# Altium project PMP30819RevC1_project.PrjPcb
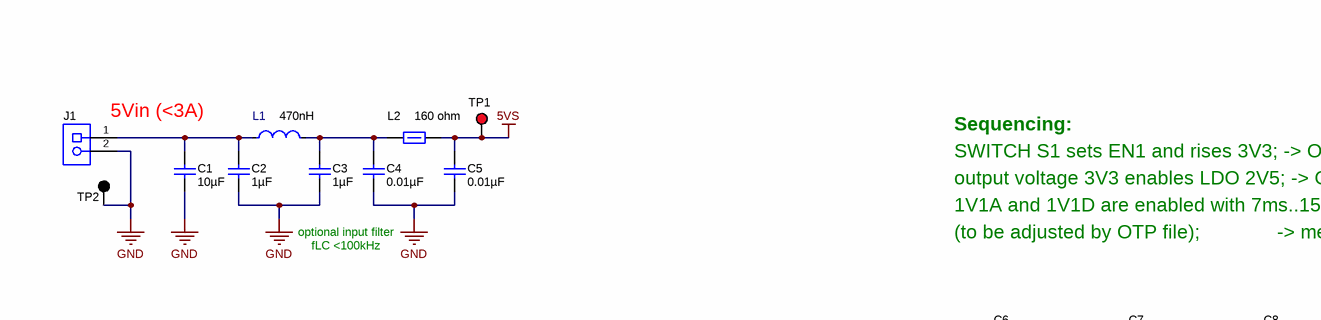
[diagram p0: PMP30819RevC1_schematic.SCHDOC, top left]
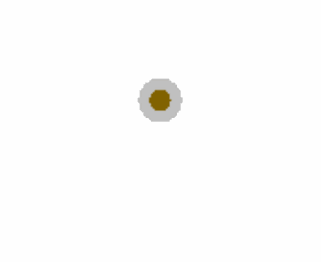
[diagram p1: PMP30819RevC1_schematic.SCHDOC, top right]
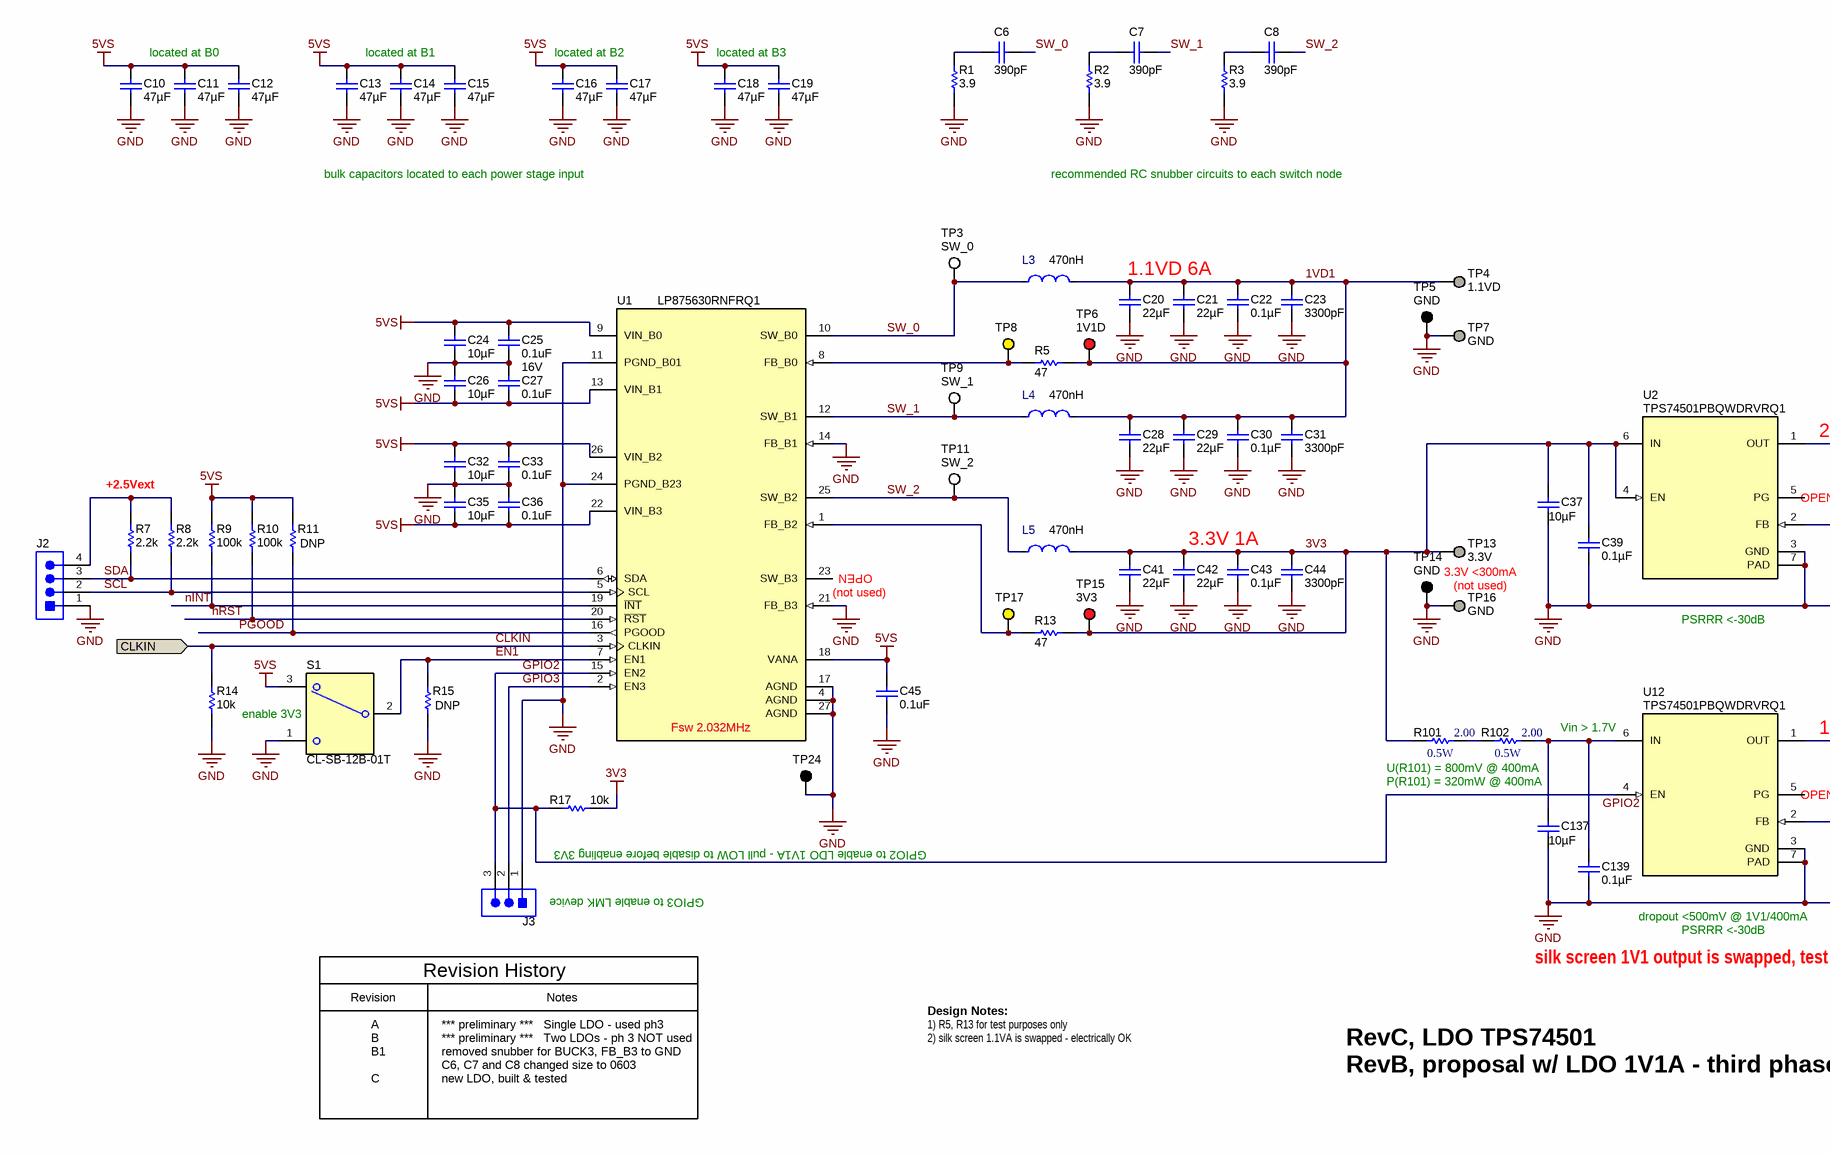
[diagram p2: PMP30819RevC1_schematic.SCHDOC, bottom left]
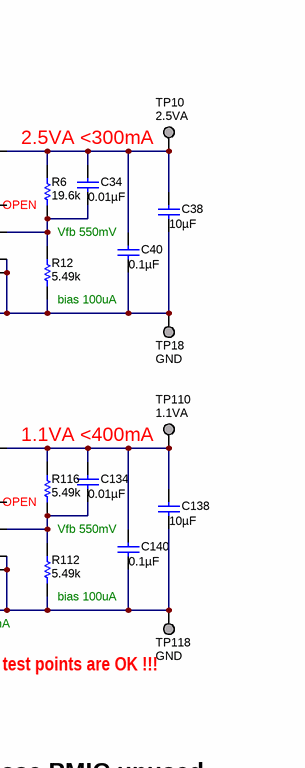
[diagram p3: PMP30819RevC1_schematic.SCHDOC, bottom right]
TID: N/A; TechSupport: http://www.ti.com/support; SCH_Rev: C1; PRJ_Title: Automotive Supply using PMIC; PRJ_Number: PMP30819; PRJ_Engineer: B.Geck; PRJ_Customer: Public Release; PCB_Rev: C1; CopyrightYear: 2020
1 sheet, 100 parts. Net scope: flat (ports and power ports of the same name join across sheets).
Board file: PMP30819RevC1_board.PcbDoc

## Sheet PMP30819RevC1_schematic.SCHDOC: PMP30819RevC1
size A3; Date: Not shown in title block; ApprovedBy: Not shown in title block; CheckedBy: Not shown in title block; Author: Not shown in title block; CompanyName: Not shown in title block; DrawnBy: B.Geck; Engineer: Not shown in title block; Organization: Not shown in title block; Address1: Not shown in title block; Address2: Not shown in title block; Address3: Not shown in title block; Address4: Not shown in title block; DocumentNumber: 1; Revision: Use project parameter SCH_Rev; SheetNumber: 1; SheetTotal: 1; PageSetup: Record=PageOptions¦CenterHorizontal=True¦CenterVertical=True¦PrintScale=0.70¦XCorrection=1.00¦YCorrection=1.00¦PrintKind=0¦BorderSize=5000000¦LeftOffset=0¦BottomOffset=0¦Orientation=2¦PaperLength=1000¦PaperWidth=1000¦Scale=100¦PaperSource=15¦PrintQuality=600¦MediaType=1¦DitherType=10¦PaperKind=A4¦PrintScaleMode=1

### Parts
C1  ValueDisplayed: 10µF  [0805_HV]  (hidden comment: CL21B106KOQNNNE)
C2  ValueDisplayed: 1µF  [0603]  (hidden comment: GRM188R71C105KA12D)
C3  ValueDisplayed: 1µF  [0603]  (hidden comment: GRM188R71C105KA12D)
C4  ValueDisplayed: 0.01µF  [0603]  (hidden comment: GRM188R71C103KA01D)
C5  ValueDisplayed: 0.01µF  [0603]  (hidden comment: GRM188R71C103KA01D)
C6  Cap_F: 390pF  [0603]  (hidden comment: GRM188R71H391KA01D)
C7  Cap_F: 390pF  [0603]  (hidden comment: GRM188R71H391KA01D)
C8  Cap_F: 390pF  [0603]  (hidden comment: GRM188R71H391KA01D)
C10  ValueDisplayed: 47µF  [1210_270]  (hidden comment: LMK325B7476MM-TR)
C11  ValueDisplayed: 47µF  [1210_270]  (hidden comment: LMK325B7476MM-TR)
C12  ValueDisplayed: 47µF  [1210_270]  (hidden comment: LMK325B7476MM-TR)
C13  ValueDisplayed: 47µF  [1210_270]  (hidden comment: LMK325B7476MM-TR)
C14  ValueDisplayed: 47µF  [1210_270]  (hidden comment: LMK325B7476MM-TR)
C15  ValueDisplayed: 47µF  [1210_270]  (hidden comment: LMK325B7476MM-TR)
C16  ValueDisplayed: 47µF  [1210_270]  (hidden comment: LMK325B7476MM-TR)
C17  ValueDisplayed: 47µF  [1210_270]  (hidden comment: LMK325B7476MM-TR)
C18  ValueDisplayed: 47µF  [1210_270]  (hidden comment: LMK325B7476MM-TR)
C19  ValueDisplayed: 47µF  [1210_270]  (hidden comment: LMK325B7476MM-TR)
C20  ValueDisplayed: 22µF  [1206_190]  (hidden comment: GRJ31CR71A226KE12L)
C21  ValueDisplayed: 22µF  [1206_190]  (hidden comment: GRJ31CR71A226KE12L)
C22  ValueDisplayed: 0.1µF  [0603]  (hidden comment: GCM188R71C104KA37J)
C23  ValueDisplayed: 3300pF  [0402L]  (hidden comment: CGA2B2X7R1H332K050BA)
C24  ValueDisplayed: 10µF  [0805_HV]  (hidden comment: CL21B106KOQNNNE)
C25  ValueDisplayed: 0.1uF  VDC_V: 16V  [0402L]  (hidden comment: C0402C104K4RACAUTO)
C26  ValueDisplayed: 10µF  [0805_HV]  (hidden comment: CL21B106KOQNNNE)
C27  ValueDisplayed: 0.1uF  [0402L]  (hidden comment: C0402C104K4RACAUTO)
C28  ValueDisplayed: 22µF  [1206_190]  (hidden comment: GRJ31CR71A226KE12L)
C29  ValueDisplayed: 22µF  [1206_190]  (hidden comment: GRJ31CR71A226KE12L)
C30  ValueDisplayed: 0.1µF  [0603]  (hidden comment: GCM188R71C104KA37J)
C31  ValueDisplayed: 3300pF  [0402L]  (hidden comment: CGA2B2X7R1H332K050BA)
C32  ValueDisplayed: 10µF  [0805_HV]  (hidden comment: CL21B106KOQNNNE)
C33  ValueDisplayed: 0.1uF  [0402L]  (hidden comment: C0402C104K4RACAUTO)
C34  ValueDisplayed: 0.01µF  [0603]  (hidden comment: GRM188R71C103KA01D)
C35  ValueDisplayed: 10µF  [0805_HV]  (hidden comment: CL21B106KOQNNNE)
C36  ValueDisplayed: 0.1uF  [0402L]  (hidden comment: C0402C104K4RACAUTO)
C37  ValueDisplayed: 10µF  [0805_HV]  (hidden comment: CL21B106KOQNNNE)
C38  ValueDisplayed: 10µF  [0805_HV]  (hidden comment: CL21B106KOQNNNE)
C39  ValueDisplayed: 0.1µF  [0603]  (hidden comment: GCM188R71C104KA37J)
C40  ValueDisplayed: 0.1µF  [0603]  (hidden comment: GCM188R71C104KA37J)
C41  ValueDisplayed: 22µF  [1206_190]  (hidden comment: GRJ31CR71A226KE12L)
C42  ValueDisplayed: 22µF  [1206_190]  (hidden comment: GRJ31CR71A226KE12L)
C43  ValueDisplayed: 0.1µF  [0603]  (hidden comment: GCM188R71C104KA37J)
C44  ValueDisplayed: 3300pF  [0402L]  (hidden comment: CGA2B2X7R1H332K050BA)
C45  ValueDisplayed: 0.1uF  [0402L]  (hidden comment: C0402C104K4RACAUTO)
C134  ValueDisplayed: 0.01µF  [0603]  (hidden comment: GRM188R71C103KA01D)
C137  ValueDisplayed: 10µF  [0805_HV]  (hidden comment: CL21B106KOQNNNE)
C138  ValueDisplayed: 10µF  [0805_HV]  (hidden comment: CL21B106KOQNNNE)
C139  ValueDisplayed: 0.1µF  [0603]  (hidden comment: GCM188R71C104KA37J)
C140  ValueDisplayed: 0.1µF  [0603]  (hidden comment: GCM188R71C104KA37J)
J1  ED555/2DS  [TERM_BLK_ED555-2DS]  (value not drawn)
J2  800-10-004-10-001000  [Mill-Max_800-10-004-10-001000]  (value not drawn)
J3  800-10-003-10-001000  [Mill-Max_800-10-003-10-001000]  (value not drawn)
L1  Ind_H: 470nH  [FP-XGL4020-471MEC_SMT_4MM0_4MM0-MFG]  (hidden comment: XGL4020-471MEC)
L2  ValueDisplayed: 160 ohm  [1206]  (hidden comment: HI1206T161R-10)
L3  Ind_H: 470nH  [FP-XGL4020-471MEC_SMT_4MM0_4MM0-MFG]  (hidden comment: XGL4020-471MEC)
L4  Ind_H: 470nH  [FP-XGL4020-471MEC_SMT_4MM0_4MM0-MFG]  (hidden comment: XGL4020-471MEC)
L5  Ind_H: 470nH  [FP-XGL4020-471MEC_SMT_4MM0_4MM0-MFG]  (hidden comment: XGL4020-471MEC)
R1  ValueDisplayed: 3.9  [0805_HV]  (hidden comment: CRCW08053R90JNEA)
R2  ValueDisplayed: 3.9  [0805_HV]  (hidden comment: CRCW08053R90JNEA)
R3  ValueDisplayed: 3.9  [0805_HV]  (hidden comment: CRCW08053R90JNEA)
R5  ValueDisplayed: 47  [0603]  (hidden comment: CRCW060347R0JNEA)
R6  ValueDisplayed: 19.6k  [0603]  (hidden comment: CRCW060319K6FKEA)
R7  ValueDisplayed: 2.2k  [0603]  (hidden comment: CRCW06032K20JNEA)
R8  ValueDisplayed: 2.2k  [0603]  (hidden comment: CRCW06032K20JNEA)
R9  ValueDisplayed: 100k  [0603]  (hidden comment: CRCW0603100KFKEA)
R10  ValueDisplayed: 100k  [0603]  (hidden comment: CRCW0603100KFKEA)
R11  DNP  [0603]
R12  ValueDisplayed: 5.49k  [0603]  (hidden comment: CRCW06035K49FKEA)
R13  ValueDisplayed: 47  [0603]  (hidden comment: CRCW060347R0JNEA)
R14  ValueDisplayed: 10k  [0603]  (hidden comment: CRCW060310K0JNEA)
R15  DNP  [0603]
R17  ValueDisplayed: 10k  [0603]  (hidden comment: CRCW060310K0JNEA)
R101  ValueDisplayed: 2.00  Value2: 0.5W  [1210M]  (hidden comment: ERJ-14BQF2R0U)
R102  ValueDisplayed: 2.00  Value2: 0.5W  [1210M]  (hidden comment: ERJ-14BQF2R0U)
R112  ValueDisplayed: 5.49k  [0603]  (hidden comment: CRCW06035K49FKEA)
R116  ValueDisplayed: 5.49k  [0603]  (hidden comment: CRCW06035K49FKEA)
S1  CL-SB-12B-01T  [SW_CL-SB-12B-01]
TP1  5010  [Keystone5010]  (value not drawn)
TP2  5011  [Keystone5011]  (value not drawn)
TP3  SW_0  [Keystone5012]
TP4  1.1VD  [Keystone1503-2]
TP5  GND  [Keystone5011]
TP6  1V1D  [Keystone5010]
TP7  GND  [Keystone1503-2]
TP8  5014  [Keystone5014]  (value not drawn)
TP9  SW_1  [Keystone5012]
TP10  2.5VA  [Keystone1503-2]
TP11  SW_2  [Keystone5012]
TP13  3.3V  [Keystone1503-2]
TP14  GND  [Keystone5011]
TP15  3V3  [Keystone5010]
TP16  GND  [Keystone1503-2]
TP17  5014  [Keystone5014]  (value not drawn)
TP18  GND  [Keystone1503-2]
TP24  5011  [Keystone5011]  (value not drawn)
TP110  1.1VA  [Keystone1503-2]
TP118  GND  [Keystone1503-2]
U1  LP875630RNFRQ1  [RNF0026C]
U2  PartNumber: TPS74501PBQWDRVRQ1  [DRV0006A]  (hidden comment: TPS74501PDRVR)
U12  PartNumber: TPS74501PBQWDRVRQ1  [DRV0006A]  (hidden comment: TPS74501PDRVR)

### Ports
CLKIN (in)

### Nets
3V3: C37.1 C39.2 C41.1 C42.1 C43.2 C44.1 L5.2 R13.2 R17.2 R101.1 TP13.1 TP15.1 U2.4(EN) U2.6(IN)
5VS: C5.1 C10.1 C11.1 C12.1 C13.1 C14.1 C15.2 C16.1 C17.1 C18.1 C19.1 C24.1 C25.2 C26.1 C27.1 C32.1 C33.2 C35.1 C36.1 C45.1 L2.2 R9.1 R10.1 R11.1 S1.3 TP1.1 U1.9(VIN_B0) U1.13(VIN_B1) U1.18(VANA) U1.22(VIN_B3) U1.26(VIN_B2)
GND: C1.2 C2.2 C3.2 C4.2 C5.2 C10.2 C11.2 C12.2 C13.2 C14.2 C15.1 C16.2 C17.2 C18.2 C19.2 C20.2 C21.2 C22.1 C23.2 C24.2 C25.1 C26.2 C27.2 C28.2 C29.2 C30.1 C31.2 C32.2 C33.1 C35.2 C36.2 C37.2 C38.2 C39.1 C40.1 C41.2 C42.2 C43.1 C44.2 C45.2 C137.2 C138.2 C139.1 C140.1 J1.2 J2.1 J3.1 R1.1 R2.1 R3.1 R12.1 R14.2 R15.1 R112.1 S1.1 TP2.1 TP5.1 TP7.1 TP14.1 TP16.1 TP18.1 TP24.1 TP118.1 U1.4(AGND) U1.11(PGND_B01) U1.14(FB_B1) U1.17(AGND) U1.21(FB_B3) U1.24(PGND_B23) U1.27(AGND) U2.3(GND) U2.7(PAD) U12.3(GND) U12.7(PAD)
1VD1: C20.1 C21.1 C22.2 C23.1 C28.1 C29.1 C30.2 C31.1 L3.2 L4.2 R5.2 TP4.1 TP6.1
CLKIN: R14.1 U1.3(CLKIN) ; port CLKIN
EN1: R15.2 S1.2(COM) U1.7(EN1)
GPIO2: J3.3 R17.1 U1.15(EN2) U12.4(EN)
GPIO3: J3.2 U1.2(EN3)
nINT: R9.2 U1.19(~{INT})
nRST: R10.2 U1.20(~{RST})
PGOOD: R11.2 U1.16(PGOOD)
SCL: J2.2 R8.2 U1.5(SCL)
SDA: J2.3 R7.2 U1.6(SDA)
SW_0: C6.1 L3.1 TP3.1 U1.10(SW_B0)
SW_1: C7.1 L4.1 TP9.1 U1.12(SW_B1)
SW_2: C8.1 L5.1 TP11.1 U1.25(SW_B2)
NetC1_1: C1.1 C2.1 J1.1 L1.1
NetC3_1: C3.1 C4.1 L1.2 L2.1
NetC6_2: C6.2 R1.2
NetC7_2: C7.2 R2.2
NetC8_2: C8.2 R3.2
NetC34_1: C34.1 C38.1 C40.2 R6.2 TP10.1 U2.1(OUT)
NetC34_2: C34.2 R6.1 R12.2 U2.2(FB)
NetC134_1: C134.1 C138.1 C140.2 R116.2 TP110.1 U12.1(OUT)
NetC134_2: C134.2 R112.2 R116.1 U12.2(FB)
NetC137_1: C137.1 C139.2 R102.2 U12.6(IN)
NetJ2_4: J2.4 R7.1 R8.1
NetR5_1: R5.1 TP8.1 U1.8(FB_B0)
NetR13_1: R13.1 TP17.1 U1.1(FB_B2)
NetR101_2: R101.2 R102.1

Not connected (* = marked no-connect by the designer): U1 23(SW_B3); U2 5(PG); U12 5(PG)

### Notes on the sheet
- (near J1) 5Vin (<3A)
- Sequencing:
- SWITCH S1 sets EN1 and rises 3V3; -> O.K.
- optional input filter
- output voltage 3V3 enables LDO 2V5; -> O.K.
- 1V1A and 1V1D are enabled with 7ms..15ms delay regarding rise of 2V5.
- (to be adjusted by OTP file);              -> measured delay around 11ms, O.K.
- fLC <100kHz
- located at B0
- located at B1
- located at B2
- located at B3
- bulk capacitors located to each power stage input
- recommended RC snubber circuits to each switch node
- 1.1VD 6A
- (near U1) 8.5Amax
- +2.5Vext
- 2.5VA <300mA
- (near U1) 1.3Amax
- 3.3V 1A
- (near R6) OPEN
- Vfb 550mV
- (near U1) (not used)
- (near U1) OPEN
- (near TP13) 3.3V <300mA
- (not used)
- (near U2) PSRRR <-30dB
- (near R12) bias 100uA
- (near S1) enable 3V3
- (near U1) Fsw 2.032MHz
- Vin > 1.7V
- 1.1VA <400mA
- U(R101) = 800mV @ 400mA
- P(R101) = 320mW @ 400mA
- (near R116) OPEN
- GPIO2 to enable LDO 1V1A - pull LOW to disable before enabling 3V3
- (near R112) bias 100uA
- (near J3) GPIO3 to enable LMK device
- (near TP118) silk screen 1V1 output is swapped, test points are OK !!!
- dropout <500mV @ 1V1/400mA
- PSRRR <-30dB
- A
- Revision
- *** preliminary ***   Single LDO - used ph3
- Revision History
- Notes
- Design Notes:
- 1) R5, R13 for test purposes only
- B
- B1
- C
- *** preliminary ***   Two LDOs - ph 3 NOT used
- removed snubber for BUCK3, FB_B3 to GND
- C6, C7 and C8 changed size to 0603
- new LDO, built & tested
- 2) silk screen 1.1VA is swapped - electrically OK
- RevB, proposal w/ LDO 1V1A - third phase PMIC unused
- RevC, LDO TPS74501

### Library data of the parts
C1 C24 C26 C32 C35 C37 C38 C137 C138 = CL21B106KOQNNNE: CAP, CERM, 10 µF, 16 V,+/- 10%, X7R, 0805; Manufacturer: Samsung Electro-Mechanics; Polarized: N; CompType: Capacitor; Value: 10uF; U/M: EA; Cap_F: 0.00001; Tolerance_%: 10; VDC_V: 16; Value2: 16V; TaMin_C: -55; TaMax_C: 125; Cap_Case: 0805; AEC Category: Q200; SizeArea_mm2: 2.5; SizeAreaWB_mm2: 6.75; SizeX_mm: 2; SizeY_mm: 1.25; SizeZ_mm: 1.45; Green_Lifecycle: Active; Green_REACh: Passed
C2 C3 = GRM188R71C105KA12D: CAP, CERM, 1 µF, 16 V,+/- 10%, X7R, 0603; Manufacturer: MuRata; Polarized: N; CompType: Capacitor; Value: 1uF; U/M: EA; Cap_F: 0.000001; Tolerance_%: 10; ESR_ohm: 0.011; Value1: 0.011 ohm; VDC_V: 16; Value2: 16V; TaMin_C: -55; TaMax_C: 125; SizeArea_mm2: 1.28; SizeAreaWB_mm2: 4.68; SizeX_mm: 1.6; SizeY_mm: 0.8; SizeZ_mm: 1; AEC Category: Q200; Green_Lifecycle: Active; Green_REACh: Passed
C4 C5 C34 C134 = GRM188R71C103KA01D: CAP, CERM, 0.01 µF, 16 V,+/- 10%, X7R, 0603; Manufacturer: MuRata; Polarized: N; CompType: Capacitor; Value: 0.01uF; U/M: EA; Cap_F: 0.00000001; Tolerance_%: 10; VDC_V: 16; Value2: 16V; TaMin_C: -55; TaMax_C: 125; SizeArea_mm2: 1.28; SizeAreaWB_mm2: 4.68; SizeX_mm: 1.6; SizeY_mm: 0.8; SizeZ_mm: 1; AEC Category: Q200; Green_Lifecycle: Active; Green_REACh: Passed
C6-C8 = CMP-0007452-4: CAP, CERM, 390 pF, 50 V, +/- 10%, X7R, 0603; Manufacturer: MuRata; TaMin_C: -55°C; Polarized: N; SizeAreaWB_mm2: 4.68; Value1: Unknown; U/M: EA; Value: 390pF; TaMax_C: 125°C; SizeZ_mm: 1; SizeX_mm: 1.6; SizeY_mm: 0.8; Value2: 50V; SizeArea_mm2: 1.28; AEC Category: Q200
C10-C19 = LMK325B7476MM-TR: CAP, CERM, 47 µF, 10 V,+/- 20%, X7R, 1210; Manufacturer: Taiyo Yuden; Polarized: N; CompType: Capacitor; Value: 47uF; U/M: EA; Cap_F: 0.000047; Tolerance_%: 20; VDC_V: 10; Value2: 10V; TaMin_C: -55; TaMax_C: 125; Cap_Case: 1210; SizeArea_mm2: 8; SizeAreaWB_mm2: 14.7; SizeX_mm: 3.2; SizeY_mm: 2.5; SizeZ_mm: 2.7; AEC Category: Q200
C20 C21 C28 C29 C41 C42 = GRJ31CR71A226KE12L: CAP, CERM, 22 µF, 10 V,+/- 10%, X7R, 1206; Manufacturer: MuRata; Polarized: N; CompType: Capacitor; Value: 22uF; U/M: EA; Cap_F: 0.000022; Tolerance_%: 10; Value2: 10V; TaMin_C: -55; TaMax_C: 125; Cap_Case: 1206; SizeArea_mm2: 5.12; SizeAreaWB_mm2: 10.92; SizeX_mm: 3.2; SizeY_mm: 1.6; SizeZ_mm: 1.9; AEC Category: Q200
C22 C30 C39 C40 C43 C139 C140 = GCM188R71C104KA37J: CAP, CERM, 0.1 µF, 16 V,+/- 10%, X7R, AEC-Q200 Grade 1, 0603; Manufacturer: MuRata; Polarized: N; CompType: Capacitor; Value: 0.1uF; U/M: EA; Cap_F: 0.0000001; Tolerance_%: 10; VDC_V: 16; Value2: 16V; TaMin_C: -55; TaMax_C: 125; AEC Category: Q200; AEC Qualified: Y; AEC Grade: 1; SizeArea_mm2: 1.28; SizeAreaWB_mm2: 4.68; SizeX_mm: 1.6; SizeY_mm: 0.8; Green_Lifecycle: Active; Green_REACh: Passed
C23 C31 C44 = CGA2B2X7R1H332K050BA: CAP, CERM, 3300 pF, 50 V,+/- 10%, X7R, AEC-Q200 Grade 1, 0402; Manufacturer: TDK; Polarized: N; CompType: Capacitor; Value: 3300pF; U/M: EA; Cap_F: 0.0000000033; Tolerance_%: 10; ESR_ohm: 0.785178; Value1: 0.785178 ohm; VDC_V: 50; Value2: 50V; IRMS_A: 0.272902; TaMin_C: -55; TaMax_C: 125; Cap_Case: 0402; SizeArea_mm2: 0.5; SizeAreaWB_mm2: 3; SizeX_mm: 1; SizeZ_mm: 0.6; AEC Category: Q200; AEC Qualified: Y; Green_Lifecycle: Active; Green_REACh: Passed
C25 = CMP-0006237-2: CAP, CERM, 0.1 uF, 16 V, +/- 10%, X7R, AEC-Q200 Grade 1, 0402; Manufacturer: Kemet; Polarized: N; CompType: Capacitor; Value: 0.1uF; U/M: EA; Cap_F: 100nF; Value1: Unknown; TaMin_C: -55°C; TaMax_C: 125°C; Cap_Case: 0402; SizeArea_mm2: 0.5; SizeAreaWB_mm2: 3; SizeX_mm: 1; SizeZ_mm: 0.6; AEC Category: Q200; AEC Qualified: Y
C27 = CMP-0006237-2: CAP, CERM, 0.1 uF, 16 V, +/- 10%, X7R, AEC-Q200 Grade 1, 0402; Manufacturer: Kemet; Polarized: N; CompType: Capacitor; Value: 0.1uF; U/M: EA; Cap_F: 100nF; Value1: Unknown; VDC_V: 16V; TaMin_C: -55°C; TaMax_C: 125°C; Cap_Case: 0402; SizeArea_mm2: 0.5; SizeAreaWB_mm2: 3; SizeX_mm: 1; SizeZ_mm: 0.6; AEC Category: Q200; AEC Qualified: Y
C33 C36 C45 = CMP-0006237-2: CAP, CERM, 0.1 uF, 16 V, +/- 10%, X7R, AEC-Q200 Grade 1, 0402; Manufacturer: Kemet; Polarized: N; Value: 0.1uF; U/M: EA; Cap_F: 100nF; Value1: Unknown; VDC_V: 16V; TaMin_C: -55°C; TaMax_C: 125°C; Cap_Case: 0402; SizeArea_mm2: 0.5; SizeAreaWB_mm2: 3; SizeX_mm: 1; SizeZ_mm: 0.6; AEC Category: Q200; AEC Qualified: Y
J1 = CMP-0074913-1: Terminal Block, 3.5mm Pitch, 2x1, TH; Manufacturer: On-Shore Technology; Cert_VDE: Y; CNHeader: False; Current_A: 6A; Green_Lifecycle: Active; Shrouded: N; Gender: Female; Green_REACh: Passed; Voltage_V: 150V; Row_Count: 1; Pitch_mm: 3.5; ContactFinish: Brass; CT: True
J2 = 800-10-004-10-001000: Header, 100mil, 4x1, TH; Manufacturer: Mill-Max; SymbolCreator: a0412235
J3 = CMP-0055086-1: Header, 100mil, 3x1, TH; Manufacturer: Mill-Max; CNHeader: TRUE; Green_Lifecycle: Active; Green_REACh: Passed; CT: FALSE
L1 L3-L5 = CMP-0087242-1: Shielded Power Inductors; Manufacturer: Coilcraft; SizeZ_mm: 2.1mm; Symbol Name: SYM-XGL4020-471MEC; Isat: 6.1A; DCR_ohm: 5.1m; Material: Composite; Irms: 19.7A; AEC Grade: Grade 1; AEC Qualified: Yes
L2 = HI1206T161R-10: Ferrite Bead, 160 ohm @ 100 MHz, 6 A, 1206; Manufacturer: Laird-Signal Integrity Products; Value: 160 ohm; Imax_A: 6; DCR_ohm: 0.018; Value1: 0.018 ohm; Value2: 6A; SizeAreaWB_mm2: 10.92; SizeArea_mm2: 5.12; SizeX_mm: 3.2; SizeY_mm: 1.6; SizeZ_mm: 1.35; ZTyp@100MHz_Ohm: 160; Ztyp@1GHz_Ohm: 127; Green_Lifecycle: Not Set; Green_REACh: Incomplete
R1-R3 = CRCW08053R90JNEA: RES, 3.9, 5%, 0.125 W, 0805; Manufacturer: Vishay-Dale; CompType: Resistor; Value: 3.9; Value_Code: 3R90; Tolerance_%: 5; Power_W: 0.125; Value2: 0.125W; VDC_V: 150; TempCo: 200 ppm/C; SizeArea_mm2: 2.5; SizeX_mm: 2; SizeY_mm: 1.25; SizeZ_mm: 1.45; EIA_Code: E24; U/M: EA; AEC Category: Q200
R5 R13 = CRCW060347R0JNEA: RES, 47, 5%, 0.1 W, 0603; Manufacturer: Vishay-Dale; CompType: Resistor; Value: 47; Value_Code: 47R0; Tolerance_%: 5; Power_W: 0.1; Value2: 0.1W; VDC_V: 75; TempCo: 200 ppm/C; EIA_Code: E24; U/M: EA; AEC Category: Q200; SizeArea_mm2: 1.28; SizeX_mm: 1.6; SizeY_mm: 0.8; SizeZ_mm: 1; Green_Lifecycle: Active; Green_REACh: Passed
R6 = CRCW060319K6FKEA: RES, 19.6 k, 1%, 0.1 W, 0603; Manufacturer: Vishay-Dale; CompType: Resistor; Value: 19.6k; Res_ohm: 19600; Value_Code: 19k6; Tolerance_%: 1; Power_W: 0.1; Value2: 0.1W; VDC_V: 75; TempCo: 100 ppm/C; SizeArea_mm2: 1.28; SizeX_mm: 1.6; SizeY_mm: 0.8; EIA_Code: E96; U/M: EA; AEC Category: Q200; Green_Lifecycle: Active; Green_REACh: Passed
R7 R8 = CRCW06032K20JNEA: RES, 2.2 k, 5%, 0.1 W, 0603; Manufacturer: Vishay-Dale; CompType: Resistor; Value: 2.2k; Res_ohm: 2200; Value_Code: 2k20; Tolerance_%: 5; Power_W: 0.1; Value2: 0.1W; VDC_V: 75; TempCo: 200 ppm/C; SizeArea_mm2: 1.28; SizeX_mm: 1.6; SizeY_mm: 0.8; SizeZ_mm: 1; EIA_Code: E24; U/M: EA; AEC Category: Q200; Green_Lifecycle: Active; Green_REACh: Passed
R9-R11 = CRCW0603100KFKEA: RES, 100 k, 1%, 0.1 W, 0603; Manufacturer: Vishay-Dale; CompType: Resistor; Value: 100k; Res_ohm: 100000; Tolerance_%: 1; Power_W: 0.1; Value2: 0.1W; VDC_V: 75; TempCo: 100 ppm/C; SizeArea_mm2: 1.28; SizeX_mm: 1.6; SizeY_mm: 0.8; EIA_Code: E96; U/M: EA; AEC Category: Q200; Green_Lifecycle: Active; Green_REACh: Passed
R12 R112 R116 = CRCW06035K49FKEA: RES, 5.49 k, 1%, 0.1 W, 0603; Manufacturer: Vishay-Dale; CompType: Resistor; Value: 5.49k; Res_ohm: 5490; Value_Code: 5k49; Tolerance_%: 1; Power_W: 0.1; Value2: 0.1W; VDC_V: 75; TempCo: 100 ppm/C; SizeArea_mm2: 1.28; SizeX_mm: 1.6; SizeY_mm: 0.8; EIA_Code: E96; U/M: EA; AEC Category: Q200; Green_Lifecycle: Active; Green_REACh: Passed
R14 R17 = CRCW060310K0JNEA: RES, 10 k, 5%, 0.1 W, 0603; Manufacturer: Vishay-Dale; CompType: Resistor; Value: 10k; Res_ohm: 10000; Value_Code: 10k0; Tolerance_%: 5; Power_W: 0.1; Value2: 0.1W; VDC_V: 75; TempCo: 200 ppm/C; SizeArea_mm2: 1.28; SizeX_mm: 1.6; SizeY_mm: 0.8; SizeZ_mm: 1; EIA_Code: E24; U/M: EA; AEC Category: Q200; Green_Lifecycle: Active; Green_REACh: Passed
R15 = CRCW0603100KFKEA: RES, 100 k, 1%, 0.1 W, 0603; Manufacturer: Vishay-Dale; CompType: Resistor; Value: 100k; Res_ohm: 100000; Tolerance_%: 1; Power_W: 0.1; Value2: 0.1W; VDC_V: 75; TempCo: 100 ppm/C; EIA_Code: E96; U/M: EA; AEC Category: Q200; SizeArea_mm2: 1.28; SizeX_mm: 1.6; SizeY_mm: 0.8; Green_Lifecycle: Active; Green_REACh: Passed
R101 R102 = ERJ-14BQF2R0U: RES, 2.00, 1%, 0.5 W, AEC-Q200 Grade 0, 1210; Manufacturer: Panasonic; CompType: Resistor; Value: 2.00; Res_ohm: 2; Value_Code: 2R00; Tolerance_%: 1; Power_W: 0.5; TempCo: 100 ppm/C; SizeArea_mm2: 8; SizeAreaWB_mm2: 14.7; SizeX_mm: 3.2; SizeY_mm: 2.5; SizeZ_mm: 1.35; EIA_Code: E96; U/M: EA; AEC Category: Q200; AEC Qualified: Y; AEC Grade: 0
S1 = CMP-0002178-2: Switch, Slide, SPDT, 0.2A, GULL, 12V, SMD; Manufacturer: Copal Electronics; CurrentRating_mA: 200A; SwitchFunction: On-On; PositionCount: 2
TP1 = CMP-0055147-1: Test Point, Multipurpose, Red, TH; Manufacturer: Keystone; CNHeader: FALSE; Green_Lifecycle: Active; Green_REACh: Passed; ContactFinish: Silver; CT: TRUE
TP2 TP24 = CMP-0055148-1: Test Point, Multipurpose, Black, TH; Manufacturer: Keystone; CNHeader: FALSE; Green_Lifecycle: Active; Green_REACh: Passed; ContactFinish: Silver; CT: TRUE
TP3 TP9 TP11 = 5012: Test Point, Multipurpose, White, TH; Manufacturer: Keystone; CompType: Test Point Loop; ContactFinish: Silver; Green_Lifecycle: Active; Green_REACh: Passed
TP4 TP7 TP10 TP13 TP16 TP18 TP110 TP118 = 1503-2: Terminal, Turret, TH, Double; Manufacturer: Keystone; CompType: Turret Terminal; U/M: EA
TP5 TP14 = 5011: Test Point, Multipurpose, Black, TH; Manufacturer: Keystone; CompType: Test Point Loop; ContactFinish: Silver; Green_Lifecycle: Active; Green_REACh: Passed
TP6 TP15 = 5010: Test Point, Multipurpose, Red, TH; Manufacturer: Keystone; CompType: Test Point Loop; ContactFinish: Silver; Green_Lifecycle: Active; Green_REACh: Passed
TP8 TP17 = CMP-0055151-1: Test Point, Multipurpose, Yellow, TH; Manufacturer: Keystone; CNHeader: FALSE; Green_Lifecycle: Active; Green_REACh: Passed; ContactFinish: Silver; CT: TRUE
U1 = CMP-0079663-3: I2C Configurable Four-Phase 8-A + 4-A + 4-A Buck Converters With Integrated Switches, RNF0026C (VQFN-HR-26); Manufacturer: Texas Instruments; AEC Category: Q200; SizeAreaWB_mm2: 27.5; SizeX_mm: 4; SizeZ_mm: 0.9; SizeArea_mm2: 18; AEC Qualified: Y; CompType: IC; SizeY_mm: 4.5
U2 U12 = CMP-0082614-1: 500-mA LDO With Power-Good, DRV0006A (WSON-6); Alternate PartNumber: TPS74501PDRVT; Alternate Manufacturer: Texas Instruments; SizeAreaWB_mm2: 9; SizeZ_mm: 0.8; SizeX_mm: 2; SizeArea_mm2: 4; CompType: IC; AEC Qualified: N; AEC Category: Q200

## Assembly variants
001: not fitted FID1 FID2 FID3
